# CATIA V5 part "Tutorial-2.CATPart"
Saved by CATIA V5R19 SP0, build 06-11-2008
Part number: Part1
Bounding box of the stored display mesh (mm): x -5 to 20, y -42.072 to 42.072, z -42 to 60
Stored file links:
  D:\Shriniwas\v5_r19\Part files\c05\c05tut2.CATPart
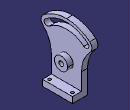
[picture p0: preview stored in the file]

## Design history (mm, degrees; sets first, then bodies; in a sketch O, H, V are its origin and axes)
Body1 (main body)
  Sketch1 on yz-plane, origin (0, 0, 0), H (0, 1, 0), V (0, 0, 1)
    construction line L1 through (0, 25.9857) direction (0, 1)
    arc A1 centre (0, 0) radius 60 from (0, 60) to (-38.5673, 45.9627) ccw
    point P3 (0, 60)
    point P4 (-38.5673, 45.9627)
    point P5 (-25, -42)
    line L2 (-25, -42) -> (-25, -3.6855)
    point P6 (-25, -3.6855)
    arc A2 centre (-32.1394, 38.3022) radius 10 from (-38.5673, 45.9627) to (-39.2828, 31.3043) ccw
    arc A3 centre (-75, -3.6855) radius 50 from (-39.2828, 31.3043) to (-25, -3.6855) cw
    point P9 (-39.2828, 31.3043)
    point P10 (-38.5673, 45.9627)
    point P11 (39.2828, 31.3043)
    point P12 (38.5673, 45.9627)
    arc A4 centre (32.1394, 38.3022) radius 10 from (38.5673, 45.9627) to (39.2828, 31.3043) cw
    point P14 (38.5673, 45.9627)
    point P15 (0, 60)
    arc A5 centre (0, 0) radius 60 from (0, 60) to (38.5673, 45.9627) cw
    point P17 (25, -3.6855)
    arc A6 centre (75, -3.6855) radius 50 from (39.2828, 31.3043) to (25, -3.6855) ccw
    point P19 (25, -42)
    line L3 (25, -42) -> (25, -3.6855)
    line L4 (-25, -42) -> (25, -42)
    construction line L5 (0, 0) -> (32.1394, 38.3022)
    construction line L6 (0, 0) -> (-32.1394, 38.3022)
    radius A5 = 60
    distance H L4 = 42
    radius A3 = 50
    radius A2 = 10
    length L4 = 50
    angle L6 L5 = 80
    vertical: L1 V, L2 V, L3 V
    coincidence: L1 O, P3 L1, A2 P4, A1 P10, P3 P15, P4 P10, P12 P14
    tangency: A3 L2, A2 A3, A2 A1
    symmetry: P9 P11 L1, P10 P12 L1, A2 A4 L1, P4 P14 L1, P3 P15 L1, A1 A5 L1, P6 P17 L1, A3 A6 L1, P5 P19 L1, L2 L3 L1
    horizontal: L4 H
  Pad1: profile Sketch1, direction (1, 0, 0), length 5, mirrored extent
  Sketch2 on end face of Pad1, origin (5, 0, 0), H (0, 1, 0), V (0, 0, 1)
    construction arc A1 centre (0, 0) radius 50 from (32.1394, 38.3022) to (-32.1394, 38.3022) ccw
    point P1 (32.1394, 38.3022)
    point P2 (-32.1394, 38.3022)
    arc A2 centre (32.1394, 38.3022) radius 5 from (35.3533, 42.1324) to (28.9254, 34.472) cw
    arc A3 centre (-32.1394, 38.3022) radius 5 from (-28.9254, 34.472) to (-35.3533, 42.1324) cw
    arc A4 centre (0, 0) radius 45 from (28.9254, 34.472) to (-28.9254, 34.472) ccw
    arc A5 centre (0, 0) radius 55 from (-35.3533, 42.1324) to (35.3533, 42.1324) cw
    reference projected arc E1 centre (-32.1394, 38.3022) radius 10 from (-38.5394, 45.986) to (-39.306, 31.3281) ccw from edge [face of Pad1 from Sketch1.A2 | end face of Pad1]
    reference projected arc E2 centre (32.1394, 38.3022) radius 10 from (39.306, 31.3281) to (38.5394, 45.986) ccw from edge [face of Pad1 from Sketch1.A4 | end face of Pad1]
    construction line L1 (0, 0) -> (32.1394, 38.3022)
    construction line L2 (0, 0) -> (-32.1394, 38.3022)
    radius A3 = 5
    tangency: A4 A3, A3 A5, A5 A2, A2 A4
    concentricity: A4 O, A5 O, P2 E1, P1 E2
  Pocket1: profile Sketch2, direction (-1, 0, 0), through (limit type 3)
  Sketch3 on end face of Pad1, origin (5, 0, 0), H (0, 1, 0), V (0, 0, 1)
    projected line E1 (-25, -42) -> (25, -42) from edge [face of Pad1 from Sketch1.L4 | end face of Pad1]
    line L1 (-25, -42) -> (-25, -32)
    line L2 (25, -42) -> (25, -32)
    line L3 (-25, -32) -> (25, -32)
    length L2 = 10
    vertical: L1 V, L2 V
    horizontal: L3 H
  Pad2: profile Sketch3, direction (1, 0, 0), length 15
  Sketch4 on end face of Pad1, origin (5, 0, 0), H (0, 1, 0), V (0, 0, 1)
    circle A1 centre (0, 0) radius 11
    circle A2 centre (0, 0) radius 4
    radius A2 = 4
    radius A1 = 11
  Pad3: profile Sketch4, direction (1, 0, 0), length 9
  Sketch5 on face of Pad2 from Sketch3.L3, origin (0, 0, -32), H (1, 0, 0), V (0, 1, 0)
    circle A1 centre (14, 19) radius 2.5
    point P1 (14, 19)
    circle A2 centre (14, -19) radius 2.5
    point P2 (14, -19)
    reference projected line E1 (20, 25) -> (20, -25) from edge [face of Pad2 from Sketch3.L3 | end face of Pad2]
    reference projected line E2 (5, -25) -> (20, -25) from edge [face of Pad2 | face of Pad2 from Sketch3.L3]
    reference projected line E3 (5, 38.4) -> (5, 0) from edge [face of Pad1 from Sketch1.A5 | end face of Pad1]
    radius A2 = 2.5
    radius A1 = 2.5
    distance E1 P2 = 6
    distance E2 P2 = 6
    distance P2 P1 = 38
    distance P1 E3 = 9
  Pocket2: profile Sketch5, direction (0, 0, -1), through (limit type 3)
